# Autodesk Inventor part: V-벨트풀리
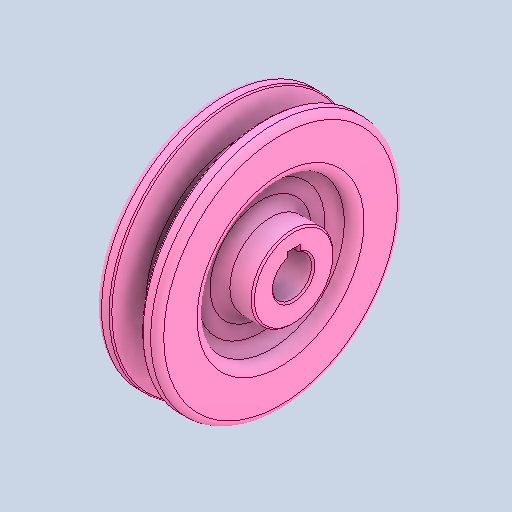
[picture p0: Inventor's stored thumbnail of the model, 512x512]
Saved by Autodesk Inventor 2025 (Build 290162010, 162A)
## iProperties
Created: 2024-07
Part Number: V-벨트풀리
Material: 강철, 탄소
Document SubType Name: Modeling
Designer: 계정
Density: 7.87 g/cm^3
Appearance: 기본값
Author: jhkim
Sending System: Autodesk Inventor 2025
Preprocessor: ST-DEVELOPER v20
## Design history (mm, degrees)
feature "솔리드1"
node "솔리드2"
